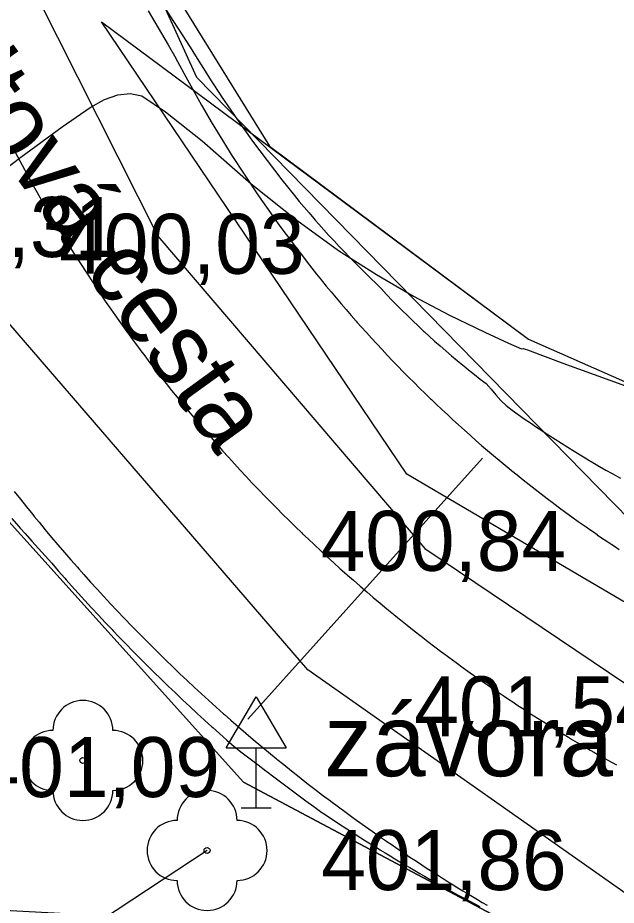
# Model space of a CAD drawing. Extents: x -574342 to -508101, y -1143544 to -1123894.
# Drawn here: x -508411.16 to -508401.18, y -1143322.98 to -1143308.19 of the extents above; entities that cross this region are included whole.
import ezdxf

# ---------------------------------------------------------------- set-up
doc = ezdxf.new("R2010")
doc.units = 0
for name, color, linetype in [('01_PARCELY_NAVRH_PC', 7, 'Continuous'), ('01_PARCELY_NAVRH_ŽP', 7, 'Continuous'), ('1000', 7, 'Continuous'), ('15', 7, 'Continuous'), ('21', 7, 'Continuous'), ('37', 7, 'Continuous'), ('52', 7, 'Continuous'), ('53', 7, 'Continuous'), ('54', 7, 'Continuous'), ('55', 7, 'Continuous'), ('60', 7, 'Continuous'), ('Level 255', 7, 'Continuous'), ('VRST HL', 7, 'Continuous')]:
    doc.layers.add(name, color=color, linetype=linetype)

msp = doc.modelspace()

# ---------------------------------------------------------------- linework, layer by layer
at = {"layer": '01_PARCELY_NAVRH_PC'}
msp.add_lwpolyline([(-508451.57, -1143168.14), (-508437.66, -1143207.58), (-508425.52, -1143241.92), (-508422.7, -1143249.88), (-508420.08, -1143265.35), (-508416.18, -1143288.91), (-508414.34, -1143296.2), (-508410.3, -1143304.94), (-508406.96, -1143310.33), (-508402.64, -1143313.55), (-508394.5, -1143317.14), (-508397.53, -1143325.93), (-508402.47, -1143323.55), (-508407.39, -1143320.93), (-508414.82, -1143312.69), (-508418.17, -1143303.49), (-508422.28, -1143289.33), (-508426.41, -1143265.09), (-508431, -1143245.85), (-508431.86, -1143242.81), (-508432.73, -1143240.34), (-508445.99, -1143206.42), (-508454.33, -1143183.49)], dxfattribs=at)
at = {"layer": '01_PARCELY_NAVRH_ŽP'}
msp.add_lwpolyline([(-508355.53, -1143335.68), (-508361.58, -1143328.14), (-508368.91, -1143322.84), (-508376.72, -1143318.72), (-508388.31, -1143315.9), (-508393.87, -1143311.09), (-508396.73, -1143306.67), (-508414.23, -1143256.72), (-508419.24, -1143259.91), (-508420.08, -1143265.35), (-508416.18, -1143288.91), (-508414.34, -1143296.2), (-508410.3, -1143304.94), (-508406.96, -1143310.33), (-508402.64, -1143313.55), (-508394.5, -1143317.14), (-508377.05, -1143323.29), (-508363.05, -1143330.55), (-508352.96, -1143343.32)], dxfattribs=at)
msp.add_lwpolyline([(-508436.6, -1143259.34), (-508429.75, -1143260.04), (-508426.41, -1143265.09), (-508422.28, -1143289.33), (-508418.17, -1143303.49), (-508414.82, -1143312.69), (-508407.39, -1143320.93), (-508402.47, -1143323.55), (-508412.73, -1143323), (-508414.59, -1143317.71), (-508420.1, -1143305.91), (-508426.78, -1143287.77), (-508433.97, -1143265.8)], close=True, dxfattribs=at)
at = {"layer": '1000'}
for points in [[(-508408.982, -1143308.08), (-508408.816, -1143308.363), (-508408.65, -1143308.646), (-508408.521, -1143308.867), (-508408.519, -1143308.869), (-508408.491, -1143308.923), (-508408.356, -1143309.177), (-508408.217, -1143309.429), (-508408.093, -1143309.65), (-508408.076, -1143309.679), (-508407.931, -1143309.927), (-508407.783, -1143310.173), (-508407.633, -1143310.415), (-508407.631, -1143310.417), (-508407.598, -1143310.471), (-508407.143, -1143311.16), (-508406.945, -1143311.443), (-508406.871, -1143311.547), (-508406.796, -1143311.65), (-508406.72, -1143311.754), (-508406.644, -1143311.857), (-508406.622, -1143311.885), (-508406.567, -1143311.959), (-508406.489, -1143312.061), (-508406.411, -1143312.162), (-508406.332, -1143312.264), (-508406.253, -1143312.364), (-508406.173, -1143312.464), (-508406.093, -1143312.564), (-508406.073, -1143312.589), (-508406.012, -1143312.663), (-508405.93, -1143312.762), (-508405.848, -1143312.86), (-508405.765, -1143312.958), (-508405.682, -1143313.055), (-508405.598, -1143313.152), (-508405.514, -1143313.248), (-508405.495, -1143313.269), (-508405.429, -1143313.344), (-508405.343, -1143313.439), (-508405.257, -1143313.534), (-508405.17, -1143313.628), (-508405.083, -1143313.722), (-508404.995, -1143313.815), (-508404.907, -1143313.908), (-508404.89, -1143313.925), (-508404.818, -1143314), (-508404.729, -1143314.092), (-508404.639, -1143314.183), (-508404.548, -1143314.273), (-508404.457, -1143314.364), (-508404.366, -1143314.453), (-508404.273, -1143314.542), (-508404.259, -1143314.556), (-508404.181, -1143314.631), (-508404.088, -1143314.719), (-508403.994, -1143314.806), (-508403.9, -1143314.893), (-508403.806, -1143314.979), (-508403.71, -1143315.065), (-508403.615, -1143315.15), (-508403.603, -1143315.161), (-508403.519, -1143315.235), (-508403.422, -1143315.319), (-508403.325, -1143315.402), (-508403.227, -1143315.485), (-508403.129, -1143315.568), (-508403.031, -1143315.65), (-508402.932, -1143315.731), (-508402.923, -1143315.738), (-508402.832, -1143315.811), (-508402.732, -1143315.891), (-508402.632, -1143315.971), (-508402.531, -1143316.05), (-508402.43, -1143316.128), (-508402.328, -1143316.206), (-508402.225, -1143316.283), (-508402.219, -1143316.288), (-508402.123, -1143316.359), (-508402.02, -1143316.435), (-508401.916, -1143316.51), (-508401.812, -1143316.585), (-508401.681, -1143316.678), (-508401.621, -1143316.72), (-508401.56, -1143316.762), (-508401.499, -1143316.804), (-508401.494, -1143316.808), (-508401.438, -1143316.846), (-508401.377, -1143316.888), (-508401.316, -1143316.929), (-508401.254, -1143316.97), (-508401.192, -1143317.011), (-508401.131, -1143317.052)], [(-508408.751, -1143307.96), (-508408.572, -1143308.236), (-508408.392, -1143308.512), (-508408.252, -1143308.727), (-508408.251, -1143308.729), (-508408.22, -1143308.781), (-508408.071, -1143309.023), (-508407.919, -1143309.262), (-508407.782, -1143309.472), (-508407.764, -1143309.499), (-508407.606, -1143309.734), (-508407.444, -1143309.966), (-508407.282, -1143310.194), (-508407.28, -1143310.196), (-508407.244, -1143310.247), (-508406.754, -1143310.893), (-508406.542, -1143311.156), (-508406.462, -1143311.253), (-508406.381, -1143311.349), (-508406.3, -1143311.444), (-508406.218, -1143311.539), (-508406.195, -1143311.565), (-508406.135, -1143311.633), (-508406.052, -1143311.726), (-508405.967, -1143311.819), (-508405.883, -1143311.911), (-508405.797, -1143312.002), (-508405.711, -1143312.093), (-508405.624, -1143312.183), (-508405.603, -1143312.205), (-508405.537, -1143312.273), (-508405.449, -1143312.361), (-508405.36, -1143312.449), (-508405.271, -1143312.536), (-508405.181, -1143312.623), (-508405.094, -1143312.712), (-508405.009, -1143312.803), (-508404.99, -1143312.822), (-508404.923, -1143312.892), (-508404.836, -1143312.981), (-508404.748, -1143313.069), (-508404.66, -1143313.156), (-508404.571, -1143313.242), (-508404.481, -1143313.328), (-508404.39, -1143313.413), (-508404.373, -1143313.428), (-508404.299, -1143313.497), (-508404.207, -1143313.58), (-508404.114, -1143313.662), (-508404.02, -1143313.744), (-508403.926, -1143313.824), (-508403.831, -1143313.904), (-508403.736, -1143313.983), (-508403.721, -1143313.995), (-508403.64, -1143314.061), (-508403.543, -1143314.138), (-508403.445, -1143314.215), (-508403.347, -1143314.29), (-508403.263, -1143314.381), (-508403.183, -1143314.477), (-508403.102, -1143314.572), (-508403.092, -1143314.583), (-508403.013, -1143314.657), (-508402.913, -1143314.73), (-508402.812, -1143314.803), (-508402.711, -1143314.874), (-508402.609, -1143314.945), (-508402.507, -1143315.014), (-508402.403, -1143315.083), (-508402.394, -1143315.089), (-508402.3, -1143315.15), (-508402.195, -1143315.217), (-508402.09, -1143315.282), (-508401.985, -1143315.348), (-508401.881, -1143315.414), (-508401.777, -1143315.479), (-508401.671, -1143315.543), (-508401.665, -1143315.547), (-508401.566, -1143315.607), (-508401.459, -1143315.669), (-508401.352, -1143315.73), (-508401.245, -1143315.79), (-508401.11, -1143315.864)], [(-508411.213, -1143316.087), (-508411.111, -1143316.217), (-508411.009, -1143316.345), (-508410.905, -1143316.473), (-508410.88, -1143316.504), (-508410.801, -1143316.6), (-508410.697, -1143316.727), (-508410.591, -1143316.853), (-508410.485, -1143316.978), (-508410.378, -1143317.103), (-508410.27, -1143317.227), (-508410.162, -1143317.351), (-508410.138, -1143317.377), (-508410.053, -1143317.473), (-508409.943, -1143317.596), (-508409.833, -1143317.717), (-508409.721, -1143317.838), (-508409.609, -1143317.959), (-508409.497, -1143318.078), (-508409.384, -1143318.197), (-508409.362, -1143318.219), (-508409.269, -1143318.316), (-508409.155, -1143318.433), (-508409.039, -1143318.55), (-508408.923, -1143318.666), (-508408.806, -1143318.782), (-508408.689, -1143318.897), (-508408.571, -1143319.011), (-508408.553, -1143319.029), (-508408.452, -1143319.125), (-508408.333, -1143319.238), (-508408.213, -1143319.35), (-508408.092, -1143319.461), (-508407.97, -1143319.572), (-508407.848, -1143319.682), (-508407.726, -1143319.791), (-508407.71, -1143319.805), (-508407.602, -1143319.9), (-508407.478, -1143320.008), (-508407.354, -1143320.115), (-508407.229, -1143320.221), (-508407.103, -1143320.327), (-508406.976, -1143320.432), (-508406.849, -1143320.536), (-508406.837, -1143320.546), (-508406.722, -1143320.64), (-508406.593, -1143320.742), (-508406.464, -1143320.844), (-508406.335, -1143320.946), (-508406.205, -1143321.046), (-508406.074, -1143321.146), (-508405.943, -1143321.245), (-508405.935, -1143321.251), (-508405.811, -1143321.343), (-508405.679, -1143321.44), (-508405.546, -1143321.537), (-508405.412, -1143321.633), (-508405.245, -1143321.751), (-508405.167, -1143321.806), (-508405.089, -1143321.86), (-508405.011, -1143321.914), (-508405.005, -1143321.918), (-508404.933, -1143321.967), (-508404.854, -1143322.021), (-508404.776, -1143322.074), (-508404.697, -1143322.127), (-508404.618, -1143322.179), (-508404.538, -1143322.231), (-508404.459, -1143322.283), (-508404.38, -1143322.335), (-508404.3, -1143322.387), (-508404.22, -1143322.438), (-508404.14, -1143322.489), (-508404.06, -1143322.54), (-508404.048, -1143322.547), (-508403.979, -1143322.59), (-508403.899, -1143322.64), (-508403.818, -1143322.69), (-508403.737, -1143322.74), (-508403.656, -1143322.789), (-508403.575, -1143322.838), (-508403.493, -1143322.887), (-508403.412, -1143322.935), (-508403.33, -1143322.983)], [(-508411.252, -1143316.54), (-508411.143, -1143316.666), (-508411.115, -1143316.697), (-508411.033, -1143316.79), (-508410.922, -1143316.914), (-508410.811, -1143317.038), (-508410.699, -1143317.16), (-508410.589, -1143317.284), (-508410.48, -1143317.409), (-508410.37, -1143317.534), (-508410.346, -1143317.561), (-508410.26, -1143317.658), (-508410.149, -1143317.781), (-508410.037, -1143317.904), (-508409.925, -1143318.026), (-508409.812, -1143318.148), (-508409.698, -1143318.269), (-508409.584, -1143318.389), (-508409.563, -1143318.412), (-508409.469, -1143318.509), (-508409.353, -1143318.628), (-508409.237, -1143318.747), (-508409.121, -1143318.865), (-508409.003, -1143318.982), (-508408.885, -1143319.098), (-508408.766, -1143319.214), (-508408.748, -1143319.232), (-508408.647, -1143319.33), (-508408.527, -1143319.445), (-508408.407, -1143319.559), (-508408.285, -1143319.672), (-508408.164, -1143319.785), (-508408.041, -1143319.897), (-508407.918, -1143320.009), (-508407.903, -1143320.022), (-508407.795, -1143320.12), (-508407.671, -1143320.23), (-508407.546, -1143320.339), (-508407.417, -1143320.444), (-508407.283, -1143320.543), (-508407.15, -1143320.642), (-508407.019, -1143320.744), (-508407.006, -1143320.753), (-508406.887, -1143320.845), (-508406.755, -1143320.945), (-508406.622, -1143321.044), (-508406.489, -1143321.143), (-508406.355, -1143321.241), (-508406.221, -1143321.339), (-508406.086, -1143321.435), (-508406.078, -1143321.441), (-508405.948, -1143321.528), (-508405.81, -1143321.619), (-508405.671, -1143321.709), (-508405.531, -1143321.799), (-508405.356, -1143321.91), (-508405.275, -1143321.961), (-508405.194, -1143322.012), (-508405.113, -1143322.062), (-508405.106, -1143322.066), (-508405.031, -1143322.112), (-508404.949, -1143322.161), (-508404.867, -1143322.21), (-508404.785, -1143322.259), (-508404.703, -1143322.308), (-508404.62, -1143322.356), (-508404.538, -1143322.404), (-508404.455, -1143322.452), (-508404.373, -1143322.5), (-508404.29, -1143322.547), (-508404.207, -1143322.595), (-508404.124, -1143322.641), (-508404.111, -1143322.648), (-508404.04, -1143322.688), (-508403.957, -1143322.734), (-508403.873, -1143322.779), (-508403.789, -1143322.825), (-508403.705, -1143322.87), (-508403.621, -1143322.914), (-508403.536, -1143322.958), (-508403.451, -1143323.002)]]:
    msp.add_lwpolyline(points, dxfattribs=at)
at = {"layer": '21'}
msp.add_lwpolyline([(-508411.237, -1143310.363), (-508411.082, -1143310.652), (-508410.924, -1143310.939), (-508410.782, -1143311.192), (-508410.763, -1143311.225), (-508410.597, -1143311.508), (-508410.428, -1143311.789), (-508410.257, -1143312.065), (-508410.255, -1143312.068), (-508410.217, -1143312.129), (-508409.697, -1143312.916), (-508409.472, -1143313.238), (-508409.387, -1143313.357), (-508409.301, -1143313.476), (-508409.215, -1143313.594), (-508409.128, -1143313.711), (-508409.103, -1143313.744), (-508409.04, -1143313.828), (-508408.952, -1143313.944), (-508408.862, -1143314.06), (-508408.773, -1143314.175), (-508408.682, -1143314.29), (-508408.591, -1143314.405), (-508408.499, -1143314.518), (-508408.476, -1143314.546), (-508408.407, -1143314.632), (-508408.313, -1143314.744), (-508408.22, -1143314.856), (-508408.125, -1143314.968), (-508408.03, -1143315.079), (-508407.934, -1143315.189), (-508407.838, -1143315.299), (-508407.817, -1143315.323), (-508407.741, -1143315.409), (-508407.643, -1143315.517), (-508407.545, -1143315.626), (-508407.446, -1143315.733), (-508407.346, -1143315.84), (-508407.246, -1143315.947), (-508407.145, -1143316.052), (-508407.126, -1143316.072), (-508407.044, -1143316.158), (-508406.942, -1143316.262), (-508406.839, -1143316.367), (-508406.736, -1143316.47), (-508406.632, -1143316.573), (-508406.527, -1143316.675), (-508406.422, -1143316.777), (-508406.406, -1143316.792), (-508406.317, -1143316.878), (-508406.21, -1143316.978), (-508406.103, -1143317.078), (-508405.996, -1143317.177), (-508405.888, -1143317.276), (-508405.779, -1143317.374), (-508405.67, -1143317.471), (-508405.657, -1143317.483), (-508405.561, -1143317.567), (-508405.45, -1143317.663), (-508405.339, -1143317.759), (-508405.228, -1143317.853), (-508405.116, -1143317.947), (-508405.004, -1143318.041), (-508404.89, -1143318.133), (-508404.88, -1143318.142), (-508404.777, -1143318.226), (-508404.663, -1143318.317), (-508404.548, -1143318.408), (-508404.433, -1143318.498), (-508404.317, -1143318.587), (-508404.201, -1143318.676), (-508404.084, -1143318.764), (-508404.077, -1143318.769), (-508403.967, -1143318.851), (-508403.849, -1143318.938), (-508403.731, -1143319.024), (-508403.612, -1143319.109), (-508403.463, -1143319.214), (-508403.394, -1143319.263), (-508403.324, -1143319.311), (-508403.255, -1143319.359), (-508403.249, -1143319.363), (-508403.185, -1143319.407), (-508403.115, -1143319.454), (-508403.046, -1143319.501), (-508402.975, -1143319.548), (-508402.905, -1143319.595), (-508402.835, -1143319.642), (-508402.764, -1143319.688), (-508402.693, -1143319.734), (-508402.622, -1143319.78), (-508402.551, -1143319.825), (-508402.48, -1143319.871), (-508402.409, -1143319.916), (-508402.398, -1143319.923), (-508402.337, -1143319.961), (-508402.265, -1143320.005), (-508402.194, -1143320.05), (-508402.122, -1143320.094), (-508402.049, -1143320.138), (-508401.977, -1143320.181), (-508401.905, -1143320.225), (-508401.832, -1143320.268), (-508401.759, -1143320.311), (-508401.687, -1143320.353), (-508401.614, -1143320.396), (-508401.54, -1143320.438), (-508401.525, -1143320.447), (-508401.467, -1143320.48), (-508401.394, -1143320.521), (-508401.32, -1143320.563), (-508401.246, -1143320.604), (-508401.173, -1143320.645)], dxfattribs=at)
at = {"layer": '37'}
for points in [[(-508473.82, -1143129.8), (-508468.34, -1143141.31), (-508458.53, -1143158.76), (-508453.13, -1143170.86), (-508439.96, -1143210.5), (-508427.56, -1143241.73), (-508421.57, -1143265.72), (-508416.35, -1143292.6), (-508412.42, -1143304.7), (-508408.82, -1143311.83)], [(-508473.82, -1143129.8), (-508468.34, -1143141.31), (-508458.53, -1143158.76), (-508453.13, -1143170.86), (-508439.96, -1143210.5), (-508427.56, -1143241.73), (-508421.57, -1143265.72), (-508416.35, -1143292.6), (-508412.42, -1143304.7), (-508408.82, -1143311.83)], [(-508408.82, -1143311.83), (-508404.37, -1143317.04), (-508398.21, -1143321.18), (-508393.66, -1143322.44), (-508393.79, -1143324.58), (-508400.56, -1143323.11), (-508406.32, -1143319.06), (-508411.41, -1143313.16), (-508415.31, -1143305.9), (-508419.33, -1143292.88), (-508424.96, -1143264.72), (-508428.49, -1143248.11), (-508430.27, -1143242.09), (-508442.28, -1143211.48), (-508455.59, -1143171.17), (-508460.82, -1143160.05), (-508470.5, -1143142.85)], [(-508408.82, -1143311.83), (-508404.37, -1143317.04), (-508398.21, -1143321.18), (-508393.66, -1143322.44), (-508393.79, -1143324.58), (-508400.56, -1143323.11), (-508406.32, -1143319.06), (-508411.41, -1143313.16), (-508415.31, -1143305.9), (-508419.33, -1143292.88), (-508424.96, -1143264.72), (-508428.49, -1143248.11), (-508430.27, -1143242.09), (-508442.28, -1143211.48), (-508455.59, -1143171.17), (-508460.82, -1143160.05), (-508470.5, -1143142.85)]]:
    msp.add_lwpolyline(points, dxfattribs=at)
at = {"layer": '52'}
for p, q in [((-508407.68, -1143320.36), (-508407.18, -1143319.51)), ((-508407.18, -1143319.51), (-508406.68, -1143320.36)), ((-508407.68, -1143320.36), (-508406.68, -1143320.36)), ((-508407.18, -1143321.36), (-508407.18, -1143320.36)), ((-508407.43, -1143321.36), (-508406.93, -1143321.36))]:
    msp.add_line(p, q, dxfattribs=at)
at = {"layer": '53'}
msp.add_line((-508407.32, -1143319.88), (-508403.41, -1143315.53), dxfattribs=at)
msp.add_line((-508407.32, -1143319.88), (-508403.41, -1143315.53), dxfattribs=at)
at = {"layer": '54'}
for centre in [(-508410.07, -1143320.57), (-508408, -1143322.07)]:
    msp.add_circle(centre, 0.05, dxfattribs=at)
for centre, start, end in [((-508410.07, -1143320.07), 0, 180), ((-508410.57, -1143320.57), 90, 270), ((-508409.57, -1143320.57), 270, 90), ((-508410.07, -1143321.07), 180, 0), ((-508408, -1143321.57), 0, 180), ((-508408.5, -1143322.07), 90, 270), ((-508407.5, -1143322.07), 270, 90), ((-508408, -1143322.57), 180, 0)]:
    msp.add_arc(centre, 0.5, start, end, dxfattribs=at)
at = {"layer": '55'}
for points in [[(-508408, -1143322.07), (-508412.54, -1143325.06), (-508424.05, -1143297.62), (-508436.1, -1143264.37)], [(-508408, -1143322.07), (-508412.54, -1143325.06), (-508424.05, -1143297.62), (-508436.1, -1143264.37)], [(-508399.15, -1143318.4), (-508408.17, -1143309.19), (-508414.22, -1143295.92)], [(-508399.15, -1143318.4), (-508408.17, -1143309.19), (-508414.22, -1143295.92)]]:
    msp.add_lwpolyline(points, dxfattribs=at)
at = {"layer": '60'}
for points in [[(-508409.76, -1143308.26), (-508402.64, -1143313.55), (-508394.5, -1143317.14), (-508378.66, -1143319), (-508370.76, -1143321.98), (-508364.58, -1143327.7), (-508357.83, -1143334.71), (-508355.73, -1143339.75)], [(-508355.73, -1143339.75), (-508359.33, -1143335.96), (-508366.15, -1143330.14), (-508372.96, -1143325.89), (-508380.12, -1143322.64), (-508395.65, -1143321.1), (-508404.67, -1143315.8), (-508409.76, -1143308.26)], [(-508409.76, -1143308.26), (-508402.64, -1143313.55), (-508394.5, -1143317.14), (-508378.66, -1143319), (-508370.76, -1143321.98), (-508364.58, -1143327.7), (-508357.83, -1143334.71), (-508355.73, -1143339.75)], [(-508355.73, -1143339.75), (-508359.33, -1143335.96), (-508366.15, -1143330.14), (-508372.96, -1143325.89), (-508380.12, -1143322.64), (-508395.65, -1143321.1), (-508404.67, -1143315.8), (-508409.76, -1143308.26)]]:
    msp.add_lwpolyline(points, dxfattribs=at)
at = {"layer": 'VRST HL'}
msp.add_lwpolyline([(-508412.016, -1143311.206), (-508411.103, -1143310.514), (-508410.414, -1143310.008), (-508409.949, -1143309.688), (-508409.708, -1143309.553), (-508409.485, -1143309.476), (-508409.279, -1143309.456), (-508409.09, -1143309.495), (-508408.691, -1143309.758), (-508408.082, -1143310.246), (-508407.264, -1143310.959), (-508406.506, -1143311.568), (-508405.81, -1143312.071), (-508405.175, -1143312.47), (-508404.557, -1143312.83), (-508403.956, -1143313.15), (-508403.371, -1143313.432), (-508402.972, -1143313.618), (-508402.758, -1143313.71), (-508402.729, -1143313.707), (-508402.695, -1143313.713), (-508402.655, -1143313.725), (-508402.611, -1143313.746), (-508402.067, -1143313.947), (-508401.024, -1143314.328)], dxfattribs=at)

# ---------------------------------------------------------------- texts
at = {"layer": '15'}
msp.add_text('asfaltová cesta', height=1.2, rotation=305.8449, dxfattribs=at).set_placement((-508414.093, -1143306.831))
msp.add_text('asfaltová cesta', height=1.2, rotation=305.8449, dxfattribs=at).set_placement((-508414.093, -1143306.831))
msp.add_text('závora', height=1.2, dxfattribs=at).set_placement((-508406.048, -1143320.832))
msp.add_text('závora', height=1.2, dxfattribs=at).set_placement((-508406.048, -1143320.832))
at = {"layer": 'Level 255'}
for s, p in [('400,31', (-508413.555, -1143312.18)), ('400,03', (-508410.465, -1143312.46)), ('400,84', (-508406.105, -1143317.41)), ('401,54', (-508404.545, -1143320.17)), ('401,09', (-508411.875, -1143321.18)), ('401,86', (-508406.095, -1143322.73))]:
    msp.add_text(s, height=1, dxfattribs=at).set_placement(p)

doc.saveas('drawing.dxf')
